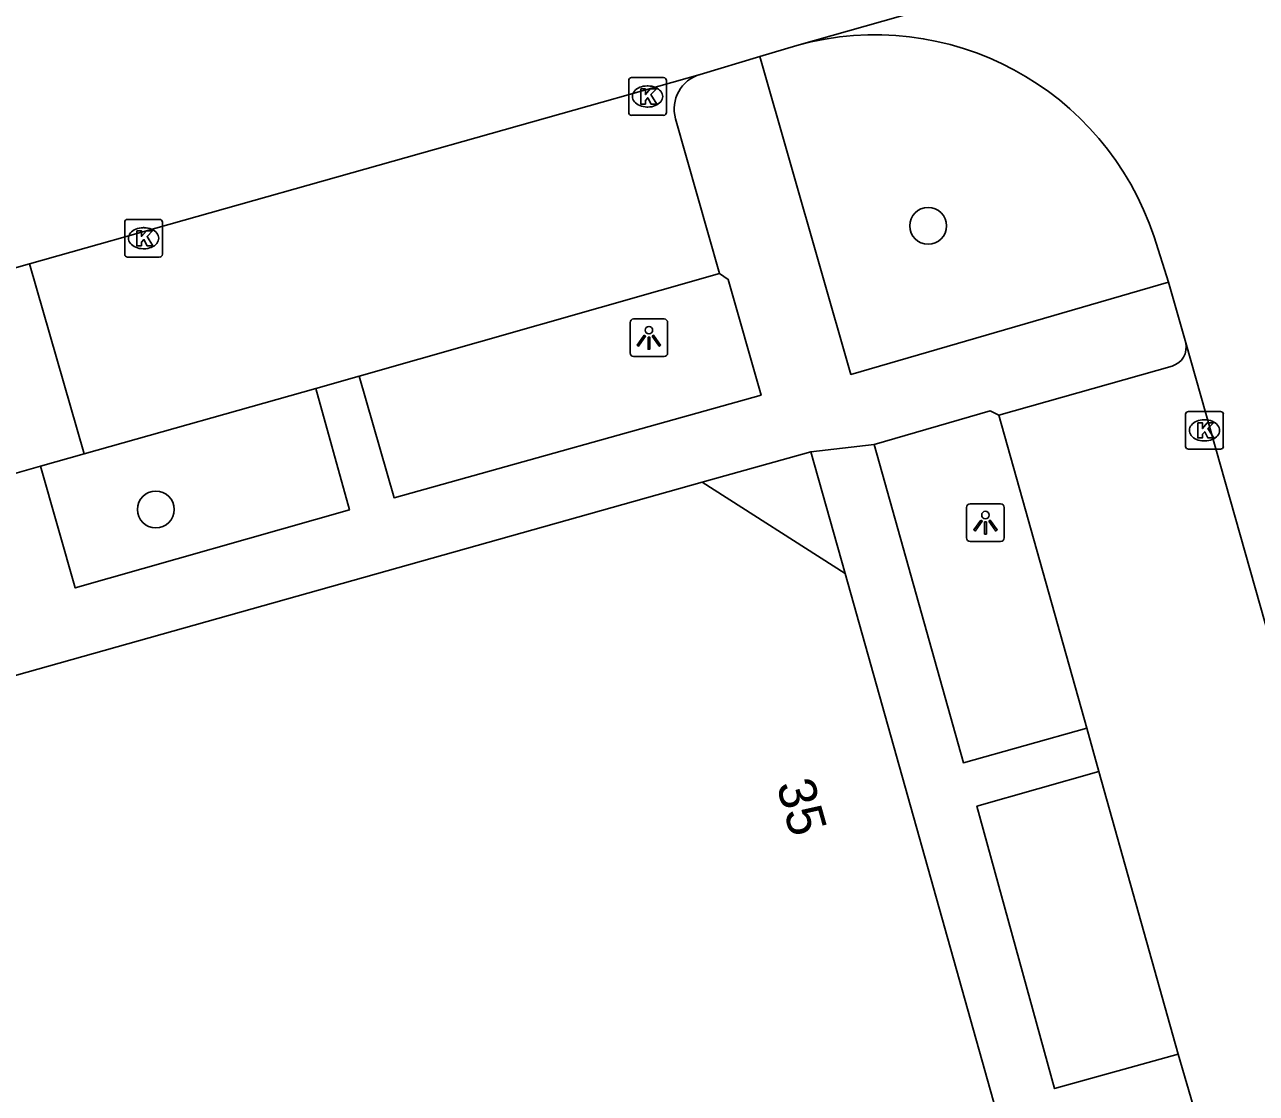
# Model space of a CAD drawing. Extents: x 159689 to 160786, y 387323 to 388339.
# Drawn here: x 160022.41 to 160055.11, y 388135.09 to 388163.45 of the extents above; entities that cross this region are included whole.
import ezdxf

# ---------------------------------------------------------------- set-up
doc = ezdxf.new("R2010")
doc.units = 0
for name, color, linetype in [('IMGEO_Boom', 7, 'Continuous'), ('IMGEO_Kolk', 7, 'Continuous'), ('IMGEO_Lichtpunt', 7, 'Continuous'), ('IMGEO_Pand', 7, 'Continuous'), ('IMGEO_Pand_nummerreeks', 7, 'Continuous'), ('IMGEO_Parkeervlak_open', 7, 'Continuous'), ('IMGEO_Rijbaan_lokaal_gesloten', 7, 'Continuous'), ('IMGEO_Rijbaan_lokaal_open', 7, 'Continuous'), ('IMGEO_Voetpad_open', 7, 'Continuous')]:
    doc.layers.add(name, color=color, linetype=linetype)

msp = doc.modelspace()

# ---------------------------------------------------------------- linework, layer by layer
at = {"layer": 'IMGEO_Boom'}
for centre in [(160046.393, 388158.109), (160025.895, 388150.584)]:
    msp.add_circle(centre, 0.489, dxfattribs=at)
at = {"layer": 'IMGEO_Kolk'}
for p, q in [((160038.521, 388162.043), (160039.373, 388162.043)), ((160038.446, 388161.117), (160038.446, 388161.969)), ((160038.934, 388161.823), (160038.959, 388161.823)), ((160039.447, 388161.969), (160039.447, 388161.117)), ((160038.957, 388161.263), (160038.932, 388161.263)), ((160039.373, 388161.043), (160038.521, 388161.043)), ((160025.07, 388157.356), (160025.07, 388158.208)), ((160025.145, 388158.282), (160025.997, 388158.282)), ((160026.071, 388158.208), (160026.071, 388157.356)), ((160025.558, 388158.062), (160025.583, 388158.062)), ((160025.581, 388157.502), (160025.556, 388157.502)), ((160025.997, 388157.282), (160025.145, 388157.282)), ((160053.228, 388152.258), (160053.228, 388153.11)), ((160053.303, 388153.184), (160054.155, 388153.184)), ((160053.716, 388152.964), (160053.741, 388152.964)), ((160054.229, 388153.11), (160054.229, 388152.258)), ((160053.739, 388152.404), (160053.714, 388152.404)), ((160054.155, 388152.184), (160053.303, 388152.184))]:
    msp.add_line(p, q, dxfattribs=at)
for points in [[(160038.521, 388162.043), (160039.373, 388162.043)], [(160038.446, 388161.117), (160038.446, 388161.969)], [(160038.767, 388161.743), (160038.89, 388161.743), (160038.89, 388161.592), (160039.02, 388161.743), (160039.184, 388161.743), (160039.038, 388161.592), (160039.191, 388161.343), (160039.039, 388161.343), (160038.954, 388161.507), (160038.89, 388161.44), (160038.89, 388161.343), (160038.767, 388161.343), (160038.767, 388161.743)], [(160039.447, 388161.969), (160039.447, 388161.117)], [(160039.373, 388161.043), (160038.521, 388161.043)], [(160025.07, 388157.356), (160025.07, 388158.208)], [(160025.145, 388158.282), (160025.997, 388158.282)], [(160026.071, 388158.208), (160026.071, 388157.356)], [(160025.391, 388157.982), (160025.514, 388157.982), (160025.514, 388157.831), (160025.644, 388157.982), (160025.808, 388157.982), (160025.662, 388157.831), (160025.815, 388157.582), (160025.663, 388157.582), (160025.578, 388157.746), (160025.514, 388157.679), (160025.514, 388157.582), (160025.391, 388157.582), (160025.391, 388157.982)], [(160025.997, 388157.282), (160025.145, 388157.282)], [(160053.228, 388152.258), (160053.228, 388153.11)], [(160053.303, 388153.184), (160054.155, 388153.184)], [(160053.549, 388152.884), (160053.672, 388152.884), (160053.672, 388152.733), (160053.802, 388152.884), (160053.966, 388152.884), (160053.82, 388152.733), (160053.973, 388152.484), (160053.821, 388152.484), (160053.736, 388152.648), (160053.672, 388152.581), (160053.672, 388152.484), (160053.549, 388152.484), (160053.549, 388152.884)], [(160054.229, 388153.11), (160054.229, 388152.258)], [(160054.155, 388152.184), (160053.303, 388152.184)]]:
    msp.add_lwpolyline(points, dxfattribs=at)
for centre, start, end in [((160038.523, 388161.967), 91.552, 178.448), ((160038.523, 388161.967), 91.552, 178.448), ((160039.371, 388161.967), 1.552, 88.448), ((160039.371, 388161.967), 1.552, 88.448), ((160038.523, 388161.119), 181.552, 268.448), ((160038.523, 388161.119), 181.552, 268.448), ((160039.371, 388161.119), 271.552, 358.448), ((160039.371, 388161.119), 271.552, 358.448), ((160025.147, 388158.206), 91.552, 178.448), ((160025.147, 388158.206), 91.552, 178.448), ((160025.995, 388158.206), 1.552, 88.448), ((160025.995, 388158.206), 1.552, 88.448), ((160025.147, 388157.358), 181.552, 268.448), ((160025.147, 388157.358), 181.552, 268.448), ((160025.995, 388157.358), 271.552, 358.448), ((160025.995, 388157.358), 271.552, 358.448), ((160053.305, 388153.108), 91.552, 178.448), ((160053.305, 388153.108), 91.552, 178.448), ((160054.153, 388153.108), 1.552, 88.448), ((160054.153, 388153.108), 1.552, 88.448), ((160053.305, 388152.26), 181.552, 268.448), ((160053.305, 388152.26), 181.552, 268.448), ((160054.153, 388152.26), 271.552, 358.448), ((160054.153, 388152.26), 271.552, 358.448)]:
    msp.add_arc(centre, 0.0765, start, end, dxfattribs=at)
for centre, major_axis, ratio, start_param, end_param in [((160038.933, 388161.543), (-0.387, 0.002), 0.722429, 4.712389, 7.853982), ((160038.958, 388161.543), (-0.39, 0.002), 0.717154, 1.570796, 4.712389), ((160025.557, 388157.782), (-0.387, 0.002), 0.722429, 4.712389, 7.853982), ((160025.582, 388157.782), (-0.39, 0.002), 0.717154, 1.570796, 4.712389), ((160053.715, 388152.684), (-0.387, 0.002), 0.722429, 4.712389, 7.853982), ((160053.74, 388152.684), (-0.39, 0.002), 0.717154, 1.570796, 4.712389)]:
    msp.add_ellipse(centre, major_axis=major_axis, ratio=ratio, start_param=start_param, end_param=end_param, dxfattribs=at)
at = {"layer": 'IMGEO_Lichtpunt'}
for p, q in [((160038.483, 388155.544), (160038.483, 388154.737)), ((160038.483, 388155.544), (160038.483, 388154.737)), ((160039.385, 388155.639), (160038.577, 388155.639)), ((160039.385, 388155.639), (160038.577, 388155.639)), ((160039.479, 388154.737), (160039.479, 388155.544)), ((160039.479, 388154.737), (160039.479, 388155.544)), ((160038.577, 388154.643), (160039.385, 388154.643)), ((160038.577, 388154.643), (160039.385, 388154.643)), ((160047.416, 388150.639), (160047.416, 388149.832)), ((160047.416, 388150.639), (160047.416, 388149.832)), ((160048.318, 388150.734), (160047.51, 388150.734)), ((160048.318, 388150.734), (160047.51, 388150.734)), ((160048.412, 388149.832), (160048.412, 388150.639)), ((160048.412, 388149.832), (160048.412, 388150.639)), ((160047.51, 388149.738), (160048.318, 388149.738)), ((160047.51, 388149.738), (160048.318, 388149.738))]:
    msp.add_line(p, q, dxfattribs=at)
for points in [[(160038.857, 388155.208), (160038.896, 388155.18), (160038.708, 388154.918), (160038.67, 388154.945), (160038.857, 388155.208)], [(160038.959, 388155.16), (160039.006, 388155.16), (160039.006, 388154.838), (160038.959, 388154.838), (160038.959, 388155.16)], [(160039.069, 388155.18), (160039.107, 388155.207), (160039.294, 388154.945), (160039.255, 388154.917), (160039.069, 388155.18)], [(160047.79, 388150.303), (160047.829, 388150.275), (160047.641, 388150.013), (160047.603, 388150.04), (160047.79, 388150.303)], [(160047.892, 388150.255), (160047.939, 388150.255), (160047.939, 388149.933), (160047.892, 388149.933), (160047.892, 388150.255)], [(160048.002, 388150.275), (160048.04, 388150.302), (160048.227, 388150.04), (160048.188, 388150.012), (160048.002, 388150.275)]]:
    msp.add_lwpolyline(points, dxfattribs=at)
for centre in [(160038.982, 388155.342), (160047.915, 388150.437)]:
    msp.add_circle(centre, 0.0994, dxfattribs=at)
for centre, start, end in [((160038.577, 388155.544), 90, 180), ((160038.577, 388155.544), 90, 180), ((160039.385, 388155.544), 0, 90), ((160039.385, 388155.544), 0, 90), ((160038.577, 388154.737), 180, 270), ((160038.577, 388154.737), 180, 270), ((160039.385, 388154.737), 270, 0), ((160039.385, 388154.737), 270, 360), ((160047.51, 388150.639), 90, 180), ((160047.51, 388150.639), 90, 180), ((160048.318, 388150.639), 0, 90), ((160048.318, 388150.639), 0, 90), ((160047.51, 388149.832), 180, 270), ((160047.51, 388149.832), 180, 270), ((160048.318, 388149.832), 270, 0), ((160048.318, 388149.832), 270, 360)]:
    msp.add_arc(centre, 0.0946, start, end, dxfattribs=at)
at = {"layer": 'IMGEO_Pand'}
for points in [[(160004.68, 388141.258), (160010.96, 388143.024), (160014.677, 388144.07), (160040.396, 388151.306)], [(160044.193, 388148.885), (160040.396, 388151.306)], [(160044.193, 388148.885), (160048.204, 388134.628)]]:
    msp.add_lwpolyline(points, dxfattribs=at)
at = {"layer": 'IMGEO_Parkeervlak_open'}
for points in [[(160040.857, 388156.843), (160031.295, 388154.122)], [(160030.14, 388153.798), (160023.996, 388152.061)], [(160048.269, 388153.084), (160050.602, 388144.782)], [(160050.925, 388143.633), (160053.034, 388136.132)]]:
    msp.add_lwpolyline(points, dxfattribs=at)
at = {"layer": 'IMGEO_Rijbaan_lokaal_gesloten'}
for points in [[(160042.911, 388162.898), (160063.98, 388168.869)], [(160052.775, 388156.62), (160052.389, 388157.815)], [(160053.232, 388155.006), (160052.775, 388156.62)], [(160058.624, 388135.972), (160053.232, 388155.006)]]:
    msp.add_lwpolyline(points, dxfattribs=at)
msp.add_arc((160044.98, 388155.378), 7.8, 18.2087, 105.3825, dxfattribs=at)
at = {"layer": 'IMGEO_Rijbaan_lokaal_open'}
for points in [[(160041.929, 388162.608), (160042.911, 388162.898)], [(160040.346, 388162.13), (160041.929, 388162.608)], [(160022.544, 388157.104), (160040.346, 388162.13)], [(160015.168, 388155.022), (160022.544, 388157.104)]]:
    msp.add_lwpolyline(points, dxfattribs=at)
at = {"layer": 'IMGEO_Voetpad_open'}
for points in [[(160052.775, 388156.62), (160044.343, 388154.17), (160041.929, 388162.608)], [(160039.688, 388160.95), (160040.857, 388156.843)], [(160022.544, 388157.104), (160023.996, 388152.061)], [(160040.857, 388156.843), (160041.09, 388156.69), (160041.96, 388153.615), (160032.221, 388150.896), (160031.295, 388154.122)], [(160052.87, 388154.391), (160048.269, 388153.084)], [(160031.295, 388154.122), (160030.14, 388153.798)], [(160030.14, 388153.798), (160031.034, 388150.572), (160023.757, 388148.502), (160022.834, 388151.732)], [(160044.964, 388152.31), (160048.041, 388153.199), (160048.269, 388153.084)], [(160044.964, 388152.31), (160043.283, 388152.118)], [(160050.602, 388144.782), (160047.329, 388143.866), (160044.964, 388152.31)], [(160023.996, 388152.061), (160022.834, 388151.732)], [(160040.396, 388151.306), (160043.283, 388152.118)], [(160043.283, 388152.118), (160044.193, 388148.885)], [(160022.834, 388151.732), (160017.624, 388150.245)], [(160050.925, 388143.633), (160050.602, 388144.782)], [(160053.034, 388136.132), (160049.749, 388135.218), (160047.687, 388142.71), (160050.925, 388143.633)], [(160053.49, 388134.554), (160053.034, 388136.132)]]:
    msp.add_lwpolyline(points, dxfattribs=at)
for centre, radius, start, end in [((160040.614, 388161.207), 0.961, 106.1865, 195.523), ((160052.72, 388154.893), 0.524, 286.5882, 12.4481)]:
    msp.add_arc(centre, radius, start, end, dxfattribs=at)

# ---------------------------------------------------------------- texts
at = {"layer": 'IMGEO_Pand_nummerreeks'}
msp.add_text('35', height=1, rotation=285.7145, dxfattribs=at).set_placement((160042.362, 388143.28))

doc.saveas('drawing.dxf')
